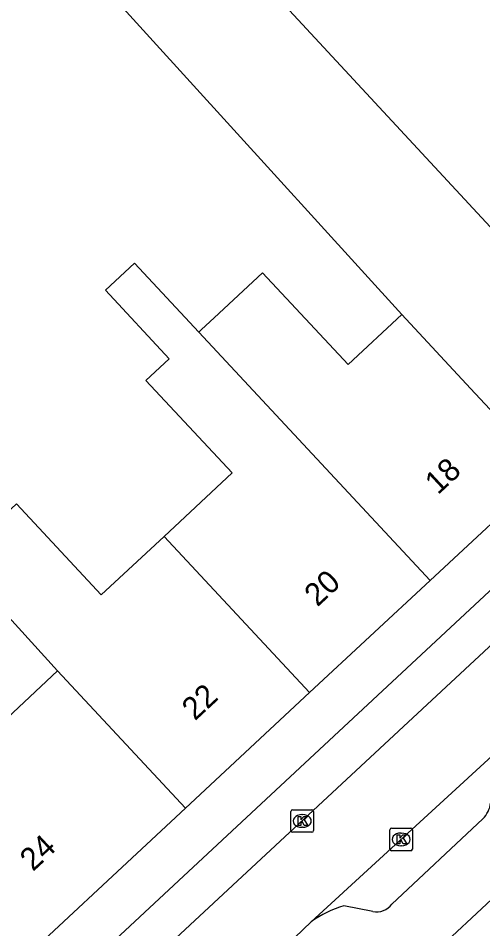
# Model space of a CAD drawing. Extents: x 161801 to 162379, y 382315 to 382832.
# Drawn here: x 161897.65 to 161918.18, y 382673.04 to 382713.31 of the extents above; entities that cross this region are included whole.
import ezdxf

# ---------------------------------------------------------------- set-up
doc = ezdxf.new("R2010")
doc.units = 0
for name, color, linetype in [('IMGEO_Kolk', 7, 'Continuous'), ('IMGEO_Pand', 7, 'Continuous'), ('IMGEO_Pand_nummerreeks', 7, 'Continuous'), ('IMGEO_Rijbaan_lokaal_open', 7, 'Continuous'), ('IMGEO_Voetpad_open', 7, 'Continuous')]:
    doc.layers.add(name, color=color, linetype=linetype)

msp = doc.modelspace()

# ---------------------------------------------------------------- linework, layer by layer
at = {"layer": 'IMGEO_Kolk'}
for p, q in [((161909.701, 382677.378), (161909.701, 382678.23)), ((161909.776, 382678.304), (161910.628, 382678.304)), ((161910.702, 382678.23), (161910.702, 382677.378)), ((161910.189, 382678.084), (161910.214, 382678.084)), ((161910.212, 382677.524), (161910.187, 382677.524)), ((161914.073, 382676.562), (161914.073, 382677.414)), ((161914.148, 382677.488), (161915, 382677.488)), ((161915.074, 382677.414), (161915.074, 382676.562)), ((161910.628, 382677.304), (161909.776, 382677.304)), ((161914.561, 382677.268), (161914.586, 382677.268)), ((161914.584, 382676.708), (161914.559, 382676.708)), ((161915, 382676.488), (161914.148, 382676.488))]:
    msp.add_line(p, q, dxfattribs=at)
for points in [[(161909.701, 382677.378), (161909.701, 382678.23)], [(161909.776, 382678.304), (161910.628, 382678.304)], [(161910.702, 382678.23), (161910.702, 382677.378)], [(161910.022, 382678.004), (161910.145, 382678.004), (161910.145, 382677.853), (161910.275, 382678.004), (161910.439, 382678.004), (161910.293, 382677.853), (161910.446, 382677.604), (161910.294, 382677.604), (161910.209, 382677.768), (161910.145, 382677.701), (161910.145, 382677.604), (161910.022, 382677.604), (161910.022, 382678.004)], [(161914.073, 382676.562), (161914.073, 382677.414)], [(161914.148, 382677.488), (161915, 382677.488)], [(161915.074, 382677.414), (161915.074, 382676.562)], [(161910.628, 382677.304), (161909.776, 382677.304)], [(161914.394, 382677.188), (161914.517, 382677.188), (161914.517, 382677.037), (161914.647, 382677.188), (161914.811, 382677.188), (161914.665, 382677.037), (161914.818, 382676.788), (161914.666, 382676.788), (161914.581, 382676.952), (161914.517, 382676.885), (161914.517, 382676.788), (161914.394, 382676.788), (161914.394, 382677.188)], [(161915, 382676.488), (161914.148, 382676.488)]]:
    msp.add_lwpolyline(points, dxfattribs=at)
for centre, start, end in [((161909.778, 382678.228), 91.552, 178.448), ((161909.778, 382678.228), 91.552, 178.448), ((161910.626, 382678.228), 1.552, 88.448), ((161910.626, 382678.228), 1.552, 88.448), ((161914.15, 382677.412), 91.552, 178.448), ((161914.15, 382677.412), 91.552, 178.448), ((161914.998, 382677.412), 1.552, 88.448), ((161914.998, 382677.412), 1.552, 88.448), ((161909.778, 382677.38), 181.552, 268.448), ((161909.778, 382677.38), 181.552, 268.448), ((161910.626, 382677.38), 271.552, 358.448), ((161910.626, 382677.38), 271.552, 358.448), ((161914.15, 382676.564), 181.552, 268.448), ((161914.15, 382676.564), 181.552, 268.448), ((161914.998, 382676.564), 271.552, 358.448), ((161914.998, 382676.564), 271.552, 358.448)]:
    msp.add_arc(centre, 0.0765, start, end, dxfattribs=at)
for centre, major_axis, ratio, start_param, end_param in [((161910.188, 382677.804), (-0.387, 0.002), 0.722429, 4.712389, 7.853982), ((161910.213, 382677.804), (-0.39, 0.002), 0.717154, 1.570796, 4.712389), ((161914.56, 382676.988), (-0.387, 0.002), 0.722429, 4.712389, 7.853982), ((161914.585, 382676.988), (-0.39, 0.002), 0.717154, 1.570796, 4.712389)]:
    msp.add_ellipse(centre, major_axis=major_axis, ratio=ratio, start_param=start_param, end_param=end_param, dxfattribs=at)
at = {"layer": 'IMGEO_Pand'}
for points in [[(161920.781, 382701.625), (161909.25, 382714.065)], [(161904.092, 382690.392), (161907.102, 382693.197), (161903.295, 382697.282), (161904.327, 382698.244), (161901.502, 382701.276), (161902.792, 382702.479), (161905.634, 382699.425)], [(161905.634, 382699.425), (161905.752, 382699.535), (161906.306, 382700.051), (161908.446, 382702.045), (161912.227, 382697.988), (161914.601, 382700.2)], [(161914.601, 382700.2), (161917.642, 382696.935), (161921.051, 382693.277)], [(161905.634, 382699.425), (161915.857, 382688.442)], [(161921.051, 382693.277), (161915.857, 382688.442)], [(161899.39, 382684.448), (161894.917, 382689.349), (161897.577, 382691.828), (161901.321, 382687.81), (161904.092, 382690.392)], [(161904.092, 382690.392), (161910.526, 382683.48)], [(161915.857, 382688.442), (161910.526, 382683.48)], [(161892.712, 382678.86), (161893.928, 382678.6), (161893.266, 382681.47), (161892.401, 382680.663), (161891.72, 382683.614), (161893.269, 382685.057), (161896.418, 382681.679), (161899.39, 382684.448)], [(161899.39, 382684.448), (161905.041, 382678.375)], [(161910.526, 382683.48), (161905.041, 382678.375)], [(161905.041, 382678.375), (161896.201, 382670.148)], [(161913.761, 382669.856), (161918.565, 382674.33)]]:
    msp.add_lwpolyline(points, dxfattribs=at)
at = {"layer": 'IMGEO_Rijbaan_lokaal_open'}
for points in [[(161895.871, 382720.8), (161914.601, 382700.2)], [(161899.049, 382666.462), (161900.203, 382668.529), (161922.425, 382689.194)], [(161918.956, 382681.014), (161910.6, 382673.34)], [(161910.6, 382673.34), (161909.875, 382672.652), (161909.162, 382671.985)]]:
    msp.add_lwpolyline(points, dxfattribs=at)
at = {"layer": 'IMGEO_Voetpad_open'}
for points in [[(161899.069, 382667.689), (161898.728, 382669.061), (161898.946, 382669.761), (161919.116, 382688.561)], [(161918.182, 382677.895), (161914.162, 382674.132)], [(161913.318, 382673.802), (161912.039, 382674.053)]]:
    msp.add_lwpolyline(points, dxfattribs=at)
for centre, radius, start, end in [((161917.363, 382678.736), 1.174, 314.234, 353.2888), ((161913.362, 382669.574), 4.671, 106.4579, 126.2574), ((161913.488, 382674.611), 0.827, 258.1287, 324.5818)]:
    msp.add_arc(centre, radius, start, end, dxfattribs=at)

# ---------------------------------------------------------------- texts
at = {"layer": 'IMGEO_Pand_nummerreeks'}
for s, rotation, p in [('18', 42.9432, (161916.201, 382692.205)), ('20', 42.9432, (161910.871, 382687.245)), ('22', 42.9459, (161905.459, 382682.208)), ('24', 42.9459, (161898.299, 382675.543))]:
    msp.add_text(s, height=1, rotation=rotation, dxfattribs=at).set_placement(p)

doc.saveas('drawing.dxf')
